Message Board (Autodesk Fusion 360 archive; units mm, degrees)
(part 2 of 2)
sketch "Sketch3" plane through (11.5, 6.5, 17.5) normal (0, 0, -1) x axis (-1, 0, 0)
  line L1 (-13.5, -1.5) -> (8.5, -1.5)
  line L2 (-13.5, -6.5) -> (-13.5, -1.5)
  line L3 (13.5, -10.75) -> (11.5, -8.75)
  line L4 (13.5, 7.25) -> (13.5, -10.75)
  line L5 (11.5, 5.25) -> (13.5, 7.25)
  line L6 (11.5, 12.5) -> (11.5, 5.25)
  line L7 (8.5, 12.5) -> (11.5, 12.5)
  line L8 (-1, -4) -> (1, -4)
  line L9 (8.5, -6.5) -> (-13.5, -6.5)
  line L10 (8.5, -1.5) -> (8.5, 12.5)
  line L11 (8.5, -12.5) -> (8.5, -6.5)
  line L12 (11.5, -12.5) -> (8.5, -12.5)
  line L13 (11.5, -8.75) -> (11.5, -12.5)
  arc A1 centre (1, -6.5) radius 2.5 clockwise from (1, -4) to (3.5, -6.5)
  arc A2 centre (-1, -6.5) radius 2.5 clockwise from (-3.5, -6.5) to (-1, -4)
  point P16 (-1, -6.5)
  point P13 (1, -6.5)
  point P14 (-3.5, -6.5)
  point P11 (3.5, -6.5)
  point P21 (8.5, -6.5)
  point P22 (-13.5, -6.5)
  horizontal L8
  tangent A1 L8
  tangent A2 L8
  coincident P16 L9
  coincident P13 L9
  coincident P14 L9
  coincident P11 L9
  dimension "d39" distance L1 L8 = 2.5
  dimension "d99" distance P11 P21 = 5
  dimension "d100" distance P14 P22 = 10
sketch "Sketch4" plane through (0, 0, 0) normal (0, -1, 0) x axis (1, 0, 0)
  line L1 (25, 30) -> (25, 5)
  line L2 (0, 35) -> (20, 35)
  line L3 (0, 0) -> (0, 35)
  line L4 (20, 0) -> (0, 0)
  line L5 (7, 19.25) -> (9, 19.25)
  line L6 (7, 15.75) -> (7, 19.25)
  line L7 (9, 15.75) -> (7, 15.75)
  line L8 (9, 19.25) -> (9, 15.75)
  line L9 (7, 15.75) -> (9, 19.25)
  line L10 (9, 15.75) -> (7, 19.25)
  line L11 (25, 30) -> (25, 5)
  line L12 (3, 35) -> (20, 35)
  line L13 (20, 0) -> (3, 0)
  line L14 (3, 0) -> (3, 35)
  circle C1 centre (13, 30.5) radius 3
  circle C2 centre (13, 4.5) radius 3
  arc A1 centre (20, 5) radius 5 clockwise from (25, 5) to (20, 0)
  arc A2 centre (20, 30) radius 5 clockwise from (20, 35) to (25, 30)
  circle C3 centre (13, 30.5) radius 3
  circle C4 centre (13, 4.5) radius 3
  arc A3 centre (20, 5) radius 5 clockwise from (25, 5) to (20, 0)
  arc A4 centre (20, 30) radius 5 clockwise from (20, 35) to (25, 30)
  point P16 (8, 17.5)
  point P17 (8, 17.5)
  point P14 (7, 15.75)
  point P15 (9, 15.75)
  point P13 (7, 19.25)
  horizontal L5
  perpendicular L5 L6
  parallel L5 L7
  parallel L6 L8
  coincident L10 P16
  coincident P16 P17
  coincident L9 P17
  dimension "d40" distance P14 P15 = 2
  dimension "d41" distance P13 P14 = 3.5
sweep "Sweep1" sketch "Sketch4" TwistAngle 0 TaperAngle 0
extrude "Extrude5" add sketch "Sketch1" profile of L2 L3 L4 L8 L9 L11 L12 L13 against normal blind 12
extrude "Extrude6" add sketch "Sketch1" profile of L2 L3 L4 L8 L9 L11 L12 L13 blind 12 from offset 35
fillet "Fillet3" radius 5
named bodies: "Connector Bracket"

design "Top/Bottom Panel"
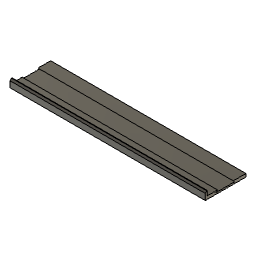
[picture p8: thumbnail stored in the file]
sketch "Sketch1" plane through (0, 0, 0) normal (1, 0, 0) x axis (0, 1, 0)
  line L1 (-38, 3) -> (-38, 7.5)
  line L2 (-34.75, 3) -> (-38, 3)
  line L3 (-38, 7.5) -> (-40, 7.5)
  line L4 (-40, 7.5) -> (-40, 0)
  line L5 (0, 0) -> (-40, 0)
  line L6 (-28, 3) -> (-34.75, 3)
  line L7 (-29.5, 1.5) -> (-28, 3)
  line L8 (-11, 1.5) -> (-29.5, 1.5)
  line L9 (-12.5, 3) -> (-11, 1.5)
  line L10 (-11, 2.1821) -> (-11, 1.5)
  line L11 (-12.5, 3) -> (0, 3)
  line L12 (0, 3) -> (0, 0)
  point P5 (0, 0)
  point P8 (0, 0)
  point P15 (0, 0)
  point P1 (0, 0)
  point P2 (-40, 7.5)
  point P4 (-38, 7.5)
  point P11 (-29.5, 1.5)
  point P12 (-11, 1.5)
  point P6 (-34.75, 3)
  point P10 (-28, 3)
  coincident P5 P8
  perpendicular L3 L4
  perpendicular L1 L3
  perpendicular L4 L5
  perpendicular L1 L2
  parallel L5 L8
  coincident P5 P15
  perpendicular L5 L12
  perpendicular L11 L12
  coincident P1 P5
  dimension "d9" distance P2 P4 = 2
  dimension "d15" distance L3 L5 = 7.5
  dimension "d25" angle L6 L7 = 45
  dimension "d26" distance P11 P12 = 18.5
  dimension "d27" angle L9 L10 = 45
  dimension "d32" angle L9 L11 = 45
  dimension "d34" distance L5 L11 = 3
  dimension "d35" distance L5 L8 = 1.5
  dimension "d36" distance L5 L6 = 3
  dimension "d37" distance L4 L12 = 40
  dimension "d39" distance P6 P10 = 6.75
  dimension "d40" distance P6 L1 = 3.25
  dimension "d42" distance P12 L12 = 11
extrude "Extrude1" new body sketch "Sketch1" profile of L1 L2 L3 L4 L5 L6 L7 L8 L9 L11 L12 along normal blind 192 bodies "Top or Bottom Panel"
chamfer "Chamfer1" distance 1.5
sketch "Sketch2" plane through (0, -40, 0) normal (0, -1, 0) x axis (1, 0, 0)
  line L1 (0, 6) -> (192, 6)
  line L2 (0, 0) -> (0, 6)
  line L3 (192, 0) -> (0, 0)
  line L4 (192, 6) -> (192, 0)
named bodies: "Top or Bottom Panel"

design "Shrouded Header" references "2x8 Surface Mount Header"
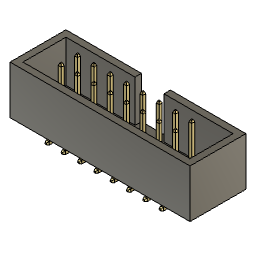
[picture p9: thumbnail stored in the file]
component_insert "Component Insert"
sketch "Sketch1" plane through (0, 0, 0) normal (0, 0, 1) x axis (1, 0, 0)
  line L1 (28, 8.7) -> (0, 8.7)
  line L2 (28, 0) -> (28, 8.7)
  line L3 (0, 0) -> (28, 0)
  line L4 (0, 8.7) -> (0, 0)
  line L5 (1, 1) -> (27, 1)
  line L6 (1, 7.7) -> (1, 1)
  line L7 (27, 7.7) -> (1, 7.7)
  line L8 (27, 1) -> (27, 7.7)
  line L9 (16.25, 7.7) -> (16.25, 8.7)
  line L10 (11.75, 7.7) -> (11.75, 8.7)
  point P10 (16.25, 8.7)
  point P11 (16.25, 7.7)
  point P12 (11.75, 8.7)
  point P13 (11.75, 7.7)
  point P1 (0, 0)
  point P5 (0, 0)
  point P2 (0, 8.7)
  point P3 (28, 8.7)
  horizontal L1
  vertical L2
  horizontal L3
  vertical L4
  coincident L1 P10
  coincident L7 P11
  perpendicular L7 L9
  coincident L1 P12
  coincident L7 P13
  perpendicular L7 L10
  coincident P1 P5
  dimension "d1" distance P2 P3 = 28
  dimension "d2" distance P2 P5 = 8.7
  dimension "d3" = 1
  dimension "d4" distance L9 L10 = 4.5
  dimension "d5" distance L2 L9 = 11.75
extrude "Extrude1" new body sketch "Sketch1" along normal blind 1
extrude "Extrude2" add sketch "Sketch1" along normal blind 7.5
move "Move1"

design "16x32 LED Panel" references "Power Plug", "Shrouded Header"
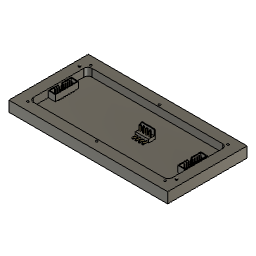
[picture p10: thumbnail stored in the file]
sketch "Sketch1" plane through (0, 0, 0) normal (0, 0, 1) x axis (1, 0, 0)
  line L1 (192, 0) -> (0, 0)
  line L2 (192, 96) -> (192, 0)
  line L3 (0, 96) -> (192, 96)
  line L4 (0, 0) -> (0, 96)
  line L5 (96, 0) -> (96, 96)
  line L6 (175, 12.5) -> (17, 12.5)
  line L7 (180, 78.5) -> (180, 17.5)
  line L8 (17, 83.5) -> (175, 83.5)
  line L9 (12, 17.5) -> (12, 78.5)
  circle C1 centre (13, 10) radius 2.5
  circle C2 centre (96, 10) radius 2.5
  circle C3 centre (179, 10) radius 2.5
  circle C4 centre (13, 86) radius 2.5
  circle C5 centre (96, 86) radius 2.5
  circle C6 centre (179, 86) radius 2.5
  arc A1 centre (17, 78.5) radius 5 clockwise from (12, 78.5) to (17, 83.5)
  arc A2 centre (175, 78.5) radius 5 clockwise from (175, 83.5) to (180, 78.5)
  arc A3 centre (175, 17.5) radius 5 clockwise from (180, 17.5) to (175, 12.5)
  arc A4 centre (17, 17.5) radius 5 clockwise from (17, 12.5) to (12, 17.5)
  circle C7 centre (7.5, 78) radius 1.25
  circle C8 centre (184.5, 18) radius 1.25
  circle C9 centre (13, 10) radius 1.25
  circle C10 centre (96, 10) radius 1.25
  circle C11 centre (179, 10) radius 1.25
  circle C12 centre (13, 86) radius 1.25
  circle C13 centre (96, 86) radius 1.25
  circle C14 centre (179, 86) radius 1.25
  point P1 (0, 0)
  point P2 (0, 0)
  point P12 (96, 96)
  point P13 (96, 0)
  point P10 (96, 86)
  point P27 (96, 48)
  point P3 (192, 0)
  point P5 (0, 96)
  point P26 (7.5, 78)
  horizontal L1
  vertical L2
  horizontal L3
  vertical L4
  coincident P1 P2
  midpoint L3 P12
  midpoint L1 P13
  coincident P10 L5
  tangent L9 A1
  tangent L8 A1
  tangent L8 A2
  tangent L7 A2
  tangent L7 A3
  tangent L6 A3
  tangent L6 A4
  tangent L9 A4
  midpoint L5 P27
  concentric C1 C9
  dimension "d1" distance P2 P3 = 192
  dimension "d2" distance P2 P5 = 96
  dimension "d3" diameter C1 = 5
  dimension "d8" distance L3 P10 = 10
  dimension "d12" radius A1 = 5
  dimension "d13" radius A2 = 5
  dimension "d14" radius A3 = 5
  dimension "d15" radius A4 = 5
  dimension "d16" diameter C7 = 2.5
  dimension "d17" distance L4 P26 = 7.5
  dimension "d18" distance L3 P26 = 18
  dimension "d21" distance L3 L8 = 12.5
  dimension "d22" distance L1 L6 = 12.5
  dimension "d23" distance L4 L9 = 12
  dimension "d24" distance L2 L7 = 12
  dimension "d33" diameter C9 = 2.5
  dimension "d6" R-Pattern1-uDistance = 166
  dimension "d7" R-Pattern1-vDistance = 76
  dimension "d20" C-Pattern1-Angle = 360
extrude "Extrude2" new body sketch "Sketch1" profile of L1 L2 L3 L4 C1 C2 C3 C4 C5 C6 L9 L8 L7 L6 A1 A2 A3 A4 C7 C8 along normal blind 12.75
extrude "Extrude3" add sketch "Sketch1" profile of L9 L8 L7 L6 A1 A2 A3 A4 along normal blind 3.45
extrude "Extrude4" add sketch "Sketch1" profile of C7 C8 along normal blind 15
fillet "Fillet1" radius 1.25
extrude "Extrude5" cut sketch "Sketch1" profile of C9 C10 C11 C12 C13 C14 blind 10 from offset 3.6
component_insert "Component Insert1"
component_insert "Component Insert2"
component_insert "Component Insert3"
extrude "Extrude1" new body sketch "Sketch1" profile of L1 L2 L3 L4 C1 C2 C3 C4 C5 C6 along normal blind 3.45

design "2x8 Surface Mount Header"
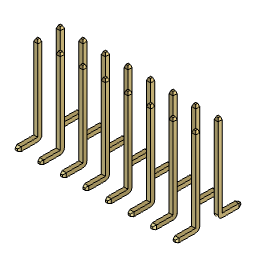
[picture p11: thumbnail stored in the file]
parameter "param_e" = 2.54 comment "Row Pitch"
parameter "param_d" = 2.54 comment "Col Pitch"
parameter "param_L" = 3.81 comment "Body Height"
parameter "param_b" = 0.46 comment "Terminal Width"
parameter "param_D" = 20.32 comment "Body Length"
parameter "param_E" = 7.36 comment "Lead Span 1"
parameter "param_E1" = 5.08 comment "Body Width"
parameter "param_L1" = 0.92 comment "Terminal Tail Length"
parameter "param_L2" = 5.84 comment "Post Length"
step "surface_mount_pin_header_straight"
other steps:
extrude "Extrude1" new body sketch "SketchBody" profile of L1 L2 L3 L4 along normal blind 20.32 (= "param_D")
chamfer "Chamfer1" distance 0.508 distance 0.508
chamfer "Chamfer2" distance 0.508 distance 0.508
sweep "Sweep1" sketch "SketchBodySlot" TwistAngle 0 TaperAngle 0
rectangular_pattern "R-Pattern1" countU 7 (= "cols - 1") uSpaceDistance 2.54 (= "param_d") vSpaceDistance 0
sweep "Sweep2" sketch "SketchPin" TwistAngle 0 TaperAngle 0
chamfer "Chamfer3" distance 0.115 (= "param_b / 4") distance 0.3067 (= "param_b / 1.5")
chamfer "Chamfer4" distance 0.115 (= "param_b / 4") distance 0.3067 (= "param_b / 1.5")
mirror "Mirror1" mirrorStitchTolerance 0.01
move "Move1"
rectangular_pattern "R-Pattern2" uSpaceDistance 2.54 (= "param_d") vSpaceDistance 0
rectangular_pattern "R-Pattern3" uSpaceDistance 2.54 (= "param_d") vSpaceDistance 0
create_component "CreateComponent1"
work_plane "WorkPlane1" AlongDistance -1.27 (= "( -param_D + param_d * ( cols - 1 ) ) / 2")
sketch "SketchBody" plane through (-1.27, 0, 0) normal (1, 0, 0) x axis (0, 0, -1)
  line L1 (-0.92, 1.27) -> (-3.81, 1.27)
  line L2 (-0.92, -3.81) -> (-0.92, 1.27)
  line L3 (-3.81, -3.81) -> (-0.92, -3.81)
  line L4 (-3.81, 1.27) -> (-3.81, -3.81)
  line L5 (-0.92, -3.81) -> (-3.81, 1.27)
  line L6 (-3.81, -3.81) -> (-0.92, 1.27)
  line L7 (-9.88, 0) -> (-0.46, 0)
  line L8 (-0.23, 2.41) -> (-0.23, 0.23)
  line L9 (0, 0) -> (-0.23, 0)
  arc A1 centre (-0.46, 0.23) radius 0.23 clockwise from (-0.23, 0.23) to (-0.46, 0)
  point P6 (-2.365, -1.27)
  point P7 (-0.23, 0)
  point P1 (0, 0)
  point P2 (-3.81, 1.27)
  point P3 (-0.92, 1.27)
  point P4 (-0.92, -3.81)
  point P9 (-0.23, 2.41)
  point P11 (-0.23, 0.23)
  point P8 (-9.88, 0)
  point P10 (-0.46, 0)
  horizontal L1
  horizontal L3
  vertical L2
  vertical L4
  midpoint L5 P6
  horizontal L7
  vertical L8
  horizontal L9
  coincident P7 L7
  coincident P7 L8
  tangent L7 A1
  tangent L8 A1
  dimension "d13" distance P1 P6 = 2.365 (= "( param_L - param_L1 ) / 2 + param_L1")
  dimension "d14" distance P1 P6 = 1.27 (= "param_E / 2 - ( param_E - param_e * ( rows - 1 ) ) / 2")
  dimension "d15" distance P2 P3 = 2.89 (= "param_L - param_L1")
  dimension "d16" distance P3 P4 = 5.08 (= "param_E1")
  dimension "d36" distance P9 P11 = 2.18 (= "param_E / 2 - param_e / 2 - param_b / 2")
  dimension "d37" distance P8 P10 = 9.42 (= "param_L + param_L2 - param_b / 2")
  dimension "d38" distance P1 P7 = 0.23 (= "param_b / 2")
  dimension "d39" radius A1 = 0.23 (= "param_b / 2")
work_plane "WorkPlane2" AlongDistance 3.81 (= "param_L")
sketch "SketchBodySlot" plane through (0, 0, 3.81) normal (0, 0, 1) x axis (1, 0, 0)
  line L1 (1.778, -3.81) -> (0.762, -3.81)
  line L2 (1.27, -3.302) -> (1.778, -3.81)
  line L3 (0.762, -3.81) -> (1.27, -3.302)
  point P1 (0, 0)
  point P4 (1.27, -3.302)
  point P2 (0.762, -3.81)
  equal L2 L3
  horizontal L1
  dimension "d24" distance P1 P4 = 1.27 (= "param_d / 2")
  dimension "d25" distance P1 P2 = 3.81 (= "param_E1 - ( param_E1 - param_e * ( rows - 1 ) ) / 2")
work_plane "WorkPlane3" AlongDistance 9.65 (= "param_L + param_L2")
sketch "SketchPin" plane through (0, 0, 9.65) normal (0, 0, 1) x axis (1, 0, 0)
  line L1 (-0.23, -0.23) -> (0.23, -0.23)
  line L2 (-0.23, 0.23) -> (-0.23, -0.23)
  line L3 (0.23, 0.23) -> (-0.23, 0.23)
  line L4 (0.23, -0.23) -> (0.23, 0.23)
  line L5 (-0.23, 0.23) -> (0.23, -0.23)
  line L6 (0.23, 0.23) -> (-0.23, -0.23)
  point P6 (0, 0)
  point P1 (0, 0)
  point P2 (0.23, -0.23)
  point P3 (-0.23, -0.23)
  point P4 (-0.23, 0.23)
  horizontal L1
  horizontal L3
  vertical L2
  vertical L4
  midpoint L5 P6
  dimension "d41" distance P1 P6 = 0
  dimension "d42" distance P1 P6 = 0
  dimension "d43" distance P2 P3 = 0.46 (= "param_b")
  dimension "d44" distance P3 P4 = 0.46 (= "param_b")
